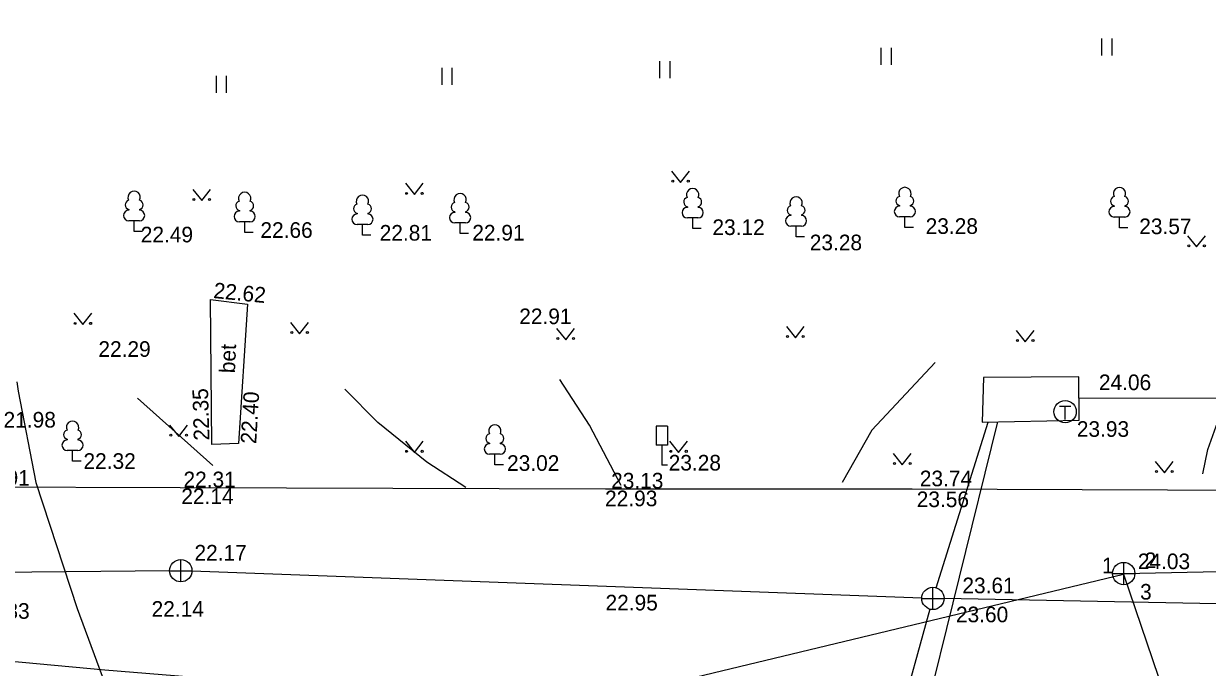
# Model space of a CAD drawing. Extents: x 714391 to 714584, y 6589993 to 6590151.
# Drawn here: x 714490.9 to 714543.9, y 6590093.4 to 6590122.2 of the extents above; entities that cross this region are included whole.
import ezdxf

# ---------------------------------------------------------------- set-up
doc = ezdxf.new("R2010")
doc.units = 0
for name, color, linetype in [('HALJASTUS', 7, 'Continuous'), ('HOONE', 7, 'Continuous'), ('HOONEDET', 7, 'Continuous'), ('HORISONTAAL', 7, 'Continuous'), ('KKAEV', 7, 'Continuous'), ('KORGUS', 7, 'Continuous'), ('KTRASS', 7, 'Continuous'), ('LIIKLUS', 7, 'Continuous'), ('PUU', 7, 'Continuous'), ('SKTRASS', 7, 'Continuous'), ('TEE', 7, 'Continuous'), ('TKAEV', 7, 'Continuous'), ('TORU NR', 7, 'Continuous'), ('TTRASS', 7, 'Continuous'), ('VTRASS', 7, 'Continuous')]:
    doc.layers.add(name, color=color, linetype=linetype)

msp = doc.modelspace()

# ---------------------------------------------------------------- linework, layer by layer
at = {"layer": 'HALJASTUS'}
for p, q in [((714539.182, 6590121.571), (714539.182, 6590120.809)), ((714539.638, 6590121.571), (714539.638, 6590120.809)), ((714529.302, 6590121.151), (714529.302, 6590120.389)), ((714529.758, 6590121.151), (714529.758, 6590120.389)), ((714519.382, 6590120.551), (714519.382, 6590119.789)), ((714519.838, 6590120.551), (714519.838, 6590119.789)), ((714509.622, 6590120.251), (714509.622, 6590119.489)), ((714510.078, 6590120.251), (714510.078, 6590119.489)), ((714499.512, 6590119.891), (714499.512, 6590119.129)), ((714499.968, 6590119.891), (714499.968, 6590119.129)), ((714519.918, 6590115.623), (714520.323, 6590115.118)), ((714520.323, 6590115.118), (714520.718, 6590115.623)), ((714498.47, 6590114.811), (714498.875, 6590114.306)), ((714498.875, 6590114.306), (714499.27, 6590114.811)), ((714507.998, 6590115.082), (714508.403, 6590114.577)), ((714508.403, 6590114.577), (714508.798, 6590115.082)), ((714543.037, 6590112.734), (714543.442, 6590112.229)), ((714543.442, 6590112.229), (714543.837, 6590112.734)), ((714493.142, 6590109.257), (714493.547, 6590108.752)), ((714493.547, 6590108.752), (714493.942, 6590109.257)), ((714502.85, 6590108.85), (714503.255, 6590108.345)), ((714503.255, 6590108.345), (714503.65, 6590108.85)), ((714514.771, 6590108.58), (714515.176, 6590108.075)), ((714515.176, 6590108.075), (714515.571, 6590108.58)), ((714525.066, 6590108.67), (714525.471, 6590108.165)), ((714525.471, 6590108.165), (714525.866, 6590108.67)), ((714535.36, 6590108.489), (714535.765, 6590107.984)), ((714535.765, 6590107.984), (714536.16, 6590108.489)), ((714497.432, 6590104.245), (714497.837, 6590103.74)), ((714497.837, 6590103.74), (714498.232, 6590104.245)), ((714507.998, 6590103.522), (714508.403, 6590103.017)), ((714508.403, 6590103.017), (714508.798, 6590103.522)), ((714519.828, 6590103.522), (714520.233, 6590103.017)), ((714520.233, 6590103.017), (714520.628, 6590103.522)), ((714529.852, 6590102.98), (714530.257, 6590102.475)), ((714530.257, 6590102.475), (714530.652, 6590102.98)), ((714541.592, 6590102.619), (714541.997, 6590102.114)), ((714541.997, 6590102.114), (714542.392, 6590102.619))]:
    msp.add_line(p, q, dxfattribs=at)
for centre, radius in [((714519.97, 6590115.174), 0.0428), ((714520.67, 6590115.174), 0.0452), ((714508.05, 6590114.632), 0.0428), ((714508.75, 6590114.632), 0.0452), ((714498.522, 6590114.361), 0.0428), ((714499.222, 6590114.361), 0.0452), ((714543.089, 6590112.284), 0.0428), ((714543.789, 6590112.284), 0.0452), ((714493.194, 6590108.807), 0.0428), ((714493.894, 6590108.807), 0.0452), ((714502.902, 6590108.401), 0.0428), ((714503.602, 6590108.401), 0.0452), ((714514.823, 6590108.13), 0.0428), ((714515.523, 6590108.13), 0.0452), ((714525.118, 6590108.22), 0.0428), ((714525.818, 6590108.22), 0.0452), ((714535.412, 6590108.039), 0.0428), ((714536.112, 6590108.039), 0.0452), ((714497.484, 6590103.795), 0.0428), ((714498.184, 6590103.795), 0.0452), ((714508.05, 6590103.073), 0.0428), ((714508.75, 6590103.073), 0.0452), ((714519.88, 6590103.073), 0.0428), ((714520.58, 6590103.073), 0.0452), ((714529.904, 6590102.531), 0.0428), ((714530.604, 6590102.531), 0.0452), ((714541.644, 6590102.17), 0.0428), ((714542.344, 6590102.17), 0.0452)]:
    msp.add_circle(centre, radius, dxfattribs=at)
at = {"layer": 'HOONE'}
msp.add_lwpolyline([(714462.976, 6590094.666), (714464.039, 6590094.043), (714487.101, 6590093.963), (714494.525, 6590093.286), (714520.217, 6590091.196), (714543.829, 6590084.007)], dxfattribs=at)
at = {"layer": 'HORISONTAAL'}
for points in [[(714543.72, 6590102.062), (714543.949, 6590103.152), (714543.949, 6590103.152), (714544.314, 6590104.204), (714544.314, 6590104.204), (714544.467, 6590104.547), (714545.44, 6590106.141), (714545.44, 6590106.141), (714545.675, 6590106.435), (714547.022, 6590107.729), (714547.022, 6590107.729)], [(714531.724, 6590107.046), (714528.888, 6590104.019), (714527.567, 6590101.674)], [(714517.657, 6590101.541), (714516.248, 6590104.249), (714514.908, 6590106.294)], [(714510.703, 6590101.446), (714508.954, 6590102.594), (714506.754, 6590104.361), (714505.276, 6590105.864)], [(714499.361, 6590102.44), (714495.986, 6590105.449)]]:
    msp.add_lwpolyline(points, dxfattribs=at)
at = {"layer": 'KKAEV'}
for p, q in [((714497.432, 6590097.723), (714498.432, 6590097.723)), ((714497.932, 6590097.223), (714497.932, 6590098.223)), ((714540.177, 6590097.097), (714540.177, 6590098.097)), ((714539.677, 6590097.597), (714540.677, 6590097.597)), ((714531.628, 6590095.983), (714531.628, 6590096.983)), ((714531.128, 6590096.483), (714532.128, 6590096.483))]:
    msp.add_line(p, q, dxfattribs=at)
for centre in [(714497.932, 6590097.723), (714540.177, 6590097.597), (714531.628, 6590096.483)]:
    msp.add_circle(centre, 0.5, dxfattribs=at)
at = {"layer": 'KTRASS'}
for p, q in [((714505.642, 6590089.275), (714540.165, 6590097.573)), ((714540.165, 6590097.573), (714543.798, 6590086.868))]:
    msp.add_line(p, q, dxfattribs=at)
msp.add_lwpolyline([(714540.177, 6590097.597), (714572.844, 6590098.291), (714583.92, 6590097.517)], dxfattribs=at)
at = {"layer": 'LIIKLUS'}
for p, q in [((714519.237, 6590104.201), (714519.237, 6590103.351)), ((714519.737, 6590104.201), (714519.237, 6590104.201)), ((714519.737, 6590104.201), (714519.737, 6590103.351)), ((714519.737, 6590103.351), (714519.237, 6590103.351)), ((714519.487, 6590103.351), (714519.487, 6590102.451)), ((714519.737, 6590102.451), (714519.487, 6590102.451))]:
    msp.add_line(p, q, dxfattribs=at)
at = {"layer": 'PUU'}
for p, q in [((714495.601, 6590113.908), (714495.601, 6590113.878)), ((714496.081, 6590113.908), (714496.081, 6590113.878)), ((714500.555, 6590113.862), (714500.555, 6590113.832)), ((714501.035, 6590113.862), (714501.035, 6590113.832)), ((714505.831, 6590113.738), (714505.831, 6590113.708)), ((714506.311, 6590113.738), (714506.311, 6590113.708)), ((714510.205, 6590113.811), (714510.205, 6590113.781)), ((714510.685, 6590113.811), (714510.685, 6590113.781)), ((714520.626, 6590114.035), (714520.626, 6590114.005)), ((714521.106, 6590114.035), (714521.106, 6590114.005)), ((714525.258, 6590113.666), (714525.258, 6590113.636)), ((714525.738, 6590113.666), (714525.738, 6590113.636)), ((714530.133, 6590114.085), (714530.133, 6590114.055)), ((714530.613, 6590114.085), (714530.613, 6590114.055)), ((714539.747, 6590114.074), (714539.747, 6590114.044)), ((714540.227, 6590114.074), (714540.227, 6590114.044)), ((714496.081, 6590113.403), (714495.601, 6590113.403)), ((714495.841, 6590112.928), (714495.841, 6590113.403)), ((714501.035, 6590113.357), (714500.555, 6590113.357)), ((714500.795, 6590112.882), (714500.795, 6590113.357)), ((714506.311, 6590113.233), (714505.831, 6590113.233)), ((714506.071, 6590112.758), (714506.071, 6590113.233)), ((714510.685, 6590113.306), (714510.205, 6590113.306)), ((714510.445, 6590112.831), (714510.445, 6590113.306)), ((714521.106, 6590113.53), (714520.626, 6590113.53)), ((714520.866, 6590113.055), (714520.866, 6590113.53)), ((714525.738, 6590113.161), (714525.258, 6590113.161)), ((714525.498, 6590112.686), (714525.498, 6590113.161)), ((714530.613, 6590113.58), (714530.133, 6590113.58)), ((714530.373, 6590113.105), (714530.373, 6590113.58)), ((714530.753, 6590113.105), (714530.373, 6590113.105)), ((714540.227, 6590113.569), (714539.747, 6590113.569)), ((714539.987, 6590113.094), (714539.987, 6590113.569)), ((714540.367, 6590113.094), (714539.987, 6590113.094)), ((714496.221, 6590112.928), (714495.841, 6590112.928)), ((714501.175, 6590112.882), (714500.795, 6590112.882)), ((714506.451, 6590112.758), (714506.071, 6590112.758)), ((714510.825, 6590112.831), (714510.445, 6590112.831)), ((714521.246, 6590113.055), (714520.866, 6590113.055)), ((714525.878, 6590112.686), (714525.498, 6590112.686)), ((714492.843, 6590103.612), (714492.843, 6590103.582)), ((714493.323, 6590103.612), (714493.323, 6590103.582)), ((714493.323, 6590103.107), (714492.843, 6590103.107)), ((714493.083, 6590102.632), (714493.083, 6590103.107)), ((714511.763, 6590103.445), (714511.763, 6590103.415)), ((714512.243, 6590103.445), (714512.243, 6590103.415)), ((714493.463, 6590102.632), (714493.083, 6590102.632)), ((714512.243, 6590102.94), (714511.763, 6590102.94)), ((714512.003, 6590102.465), (714512.003, 6590102.94)), ((714512.383, 6590102.465), (714512.003, 6590102.465))]:
    msp.add_line(p, q, dxfattribs=at)
for centre, radius, start, end in [((714495.841, 6590114.448), 0.277, 332.5799, 207.4201), ((714500.795, 6590114.402), 0.277, 332.5799, 207.4201), ((714520.866, 6590114.575), 0.277, 332.5799, 207.4201), ((714530.373, 6590114.625), 0.277, 332.5799, 207.4201), ((714539.987, 6590114.614), 0.277, 332.5799, 207.4201), ((714495.651, 6590114.116), 0.212, 105.2441, 257.079), ((714496.031, 6590114.116), 0.212, 282.921, 74.7559), ((714500.605, 6590114.07), 0.212, 105.2441, 257.079), ((714500.985, 6590114.07), 0.212, 282.921, 74.7559), ((714505.881, 6590113.946), 0.212, 105.2441, 257.079), ((714506.071, 6590114.278), 0.277, 332.5799, 207.4201), ((714506.261, 6590113.946), 0.212, 282.921, 74.7559), ((714510.255, 6590114.019), 0.212, 105.2441, 257.079), ((714510.445, 6590114.351), 0.277, 332.5799, 207.4201), ((714510.635, 6590114.019), 0.212, 282.921, 74.7559), ((714520.676, 6590114.243), 0.212, 105.2441, 257.079), ((714521.056, 6590114.243), 0.212, 282.921, 74.7559), ((714525.498, 6590114.206), 0.277, 332.5799, 207.4201), ((714530.183, 6590114.293), 0.212, 105.2441, 257.079), ((714530.563, 6590114.293), 0.212, 282.921, 74.7559), ((714539.797, 6590114.281), 0.212, 105.2441, 257.079), ((714540.177, 6590114.281), 0.212, 282.921, 74.7559), ((714495.603, 6590113.641), 0.237, 90, 270), ((714496.078, 6590113.641), 0.237, 270, 90), ((714500.557, 6590113.595), 0.237, 90, 270), ((714501.032, 6590113.595), 0.237, 270, 90), ((714505.833, 6590113.471), 0.237, 90, 270), ((714506.308, 6590113.471), 0.237, 270, 90), ((714510.207, 6590113.544), 0.237, 90, 270), ((714510.682, 6590113.544), 0.237, 270, 90), ((714520.628, 6590113.768), 0.237, 90, 270), ((714521.103, 6590113.768), 0.237, 270, 90), ((714525.26, 6590113.399), 0.237, 90, 270), ((714525.308, 6590113.874), 0.212, 105.2441, 257.079), ((714525.735, 6590113.399), 0.237, 270, 90), ((714525.688, 6590113.874), 0.212, 282.921, 74.7559), ((714530.135, 6590113.818), 0.237, 90, 270), ((714530.61, 6590113.818), 0.237, 270, 90), ((714539.749, 6590113.806), 0.237, 90, 270), ((714540.224, 6590113.806), 0.237, 270, 90), ((714493.083, 6590104.152), 0.277, 332.5799, 207.4201), ((714512.003, 6590103.985), 0.277, 332.5799, 207.4201), ((714492.845, 6590103.345), 0.237, 90, 270), ((714492.893, 6590103.82), 0.212, 105.2441, 257.079), ((714493.32, 6590103.345), 0.237, 270, 90), ((714493.273, 6590103.82), 0.212, 282.921, 74.7559), ((714511.813, 6590103.652), 0.212, 105.2441, 257.079), ((714512.193, 6590103.652), 0.212, 282.921, 74.7559), ((714511.765, 6590103.178), 0.237, 90, 270), ((714512.24, 6590103.178), 0.237, 270, 90)]:
    msp.add_arc(centre, radius, start, end, dxfattribs=at)
at = {"layer": 'SKTRASS'}
for p, q in [((714531.777, 6590096.96), (714534.097, 6590104.384)), ((714497.432, 6590097.718), (714464.189, 6590097.372)), ((714531.128, 6590096.501), (714498.432, 6590097.705)), ((714579.087, 6590095.548), (714532.128, 6590096.473))]:
    msp.add_line(p, q, dxfattribs=at)
msp.add_lwpolyline([(714531.495, 6590096.001), (714522.972, 6590065.168), (714519.718, 6590053.426), (714509.807, 6590017.772), (714505.951, 6590002.864)], dxfattribs=at)
at = {"layer": 'TEE'}
for points in [[(714583.92, 6590101.143), (714565.419, 6590101.225), (714549.748, 6590101.3), (714530.696, 6590101.382), (714516.957, 6590101.382), (714497.906, 6590101.442), (714488.527, 6590101.467), (714476.238, 6590101.479), (714465.964, 6590101.492), (714465.149, 6590101.593), (714461.989, 6590102.308), (714461.271, 6590102.628), (714460.534, 6590103.105), (714459.97, 6590103.737), (714459.406, 6590104.596), (714458.782, 6590106.528), (714458.59, 6590109.02), (714468.756, 6590132.53), (714474.437, 6590144.828), (714474.939, 6590145.152), (714475.17, 6590145.792), (714474.999, 6590146.077), (714477.095, 6590151.075)], [(714500.515, 6590103.431), (714499.32, 6590103.382), (714499.26, 6590109.881), (714500.921, 6590109.666), (714500.515, 6590103.431)]]:
    msp.add_lwpolyline(points, dxfattribs=at)
at = {"layer": 'TKAEV'}
for p, q in [((714537.303, 6590105.098), (714537.803, 6590105.098)), ((714537.553, 6590104.498), (714537.553, 6590105.098))]:
    msp.add_line(p, q, dxfattribs=at)
msp.add_circle((714537.553, 6590104.848), 0.5, dxfattribs=at)
at = {"layer": 'TTRASS'}
msp.add_lwpolyline([(714538.185, 6590104.47), (714538.167, 6590106.414), (714533.889, 6590106.377), (714533.834, 6590104.378)], close=True, dxfattribs=at)
for points in [[(714583.92, 6590105.531), (714538.176, 6590105.447)], [(714510.928, 6590008.703), (714512.829, 6590017.079), (714522.511, 6590055.684), (714522.522, 6590055.681), (714534.537, 6590104.393)]]:
    msp.add_lwpolyline(points, dxfattribs=at)
at = {"layer": 'VTRASS'}
msp.add_lwpolyline([(714490.586, 6590106.186), (714490.652, 6590105.776), (714491.439, 6590101.677), (714493.283, 6590096.028), (714496.505, 6590087.34)], dxfattribs=at)

# ---------------------------------------------------------------- texts
at = {"layer": 'HOONEDET'}
msp.add_text('bet', height=0.7, rotation=87.8184, dxfattribs=at).set_placement((714500.361, 6590106.564))
at = {"layer": 'KORGUS'}
for s, p in [('22.49', (714496.139, 6590112.436)), ('22.66', (714501.499, 6590112.638)), ('22.81', (714506.843, 6590112.514)), ('22.91', (714510.991, 6590112.519)), ('23.12', (714521.751, 6590112.766)), ('23.28', (714531.303, 6590112.816)), ('23.57', (714540.872, 6590112.805)), ('23.28', (714526.112, 6590112.081)), ('22.91', (714513.095, 6590108.771)), ('22.29', (714494.241, 6590107.307)), ('24.06', (714539.065, 6590105.815)), ('21.98', (714489.993, 6590104.138)), ('23.93', (714538.076, 6590103.723)), ('22.32', (714493.573, 6590102.286)), ('23.02', (714512.549, 6590102.198)), ('23.28', (714519.79, 6590102.213)), ('21.91', (714488.827, 6590101.533)), ('22.31', (714498.053, 6590101.462)), ('23.13', (714517.212, 6590101.409)), ('23.74', (714531.041, 6590101.507)), ('22.14', (714497.955, 6590100.712)), ('22.93', (714516.939, 6590100.613)), ('23.56', (714530.903, 6590100.573)), ('22.17', (714498.546, 6590098.179)), ('24.03', (714540.809, 6590097.793)), ('23.61', (714532.949, 6590096.714)), ('22.95', (714516.961, 6590095.944)), ('21.83', (714488.82, 6590095.571)), ('22.14', (714496.624, 6590095.66)), ('23.60', (714532.66, 6590095.414))]:
    msp.add_text(s, height=0.7, dxfattribs=at).set_placement(p)
for s, rotation, p in [('22.62', 354.4064, (714499.374, 6590109.944)), ('22.35', 91.6847, (714499.217, 6590103.566)), ('22.40', 86.5601, (714501.309, 6590103.393))]:
    msp.add_text(s, height=0.7, rotation=rotation, dxfattribs=at).set_placement(p)
at = {"layer": 'TORU NR'}
for s, p in [('1', (714539.2, 6590097.607)), ('2', (714541.114, 6590097.843)), ('3', (714540.91, 6590096.43))]:
    msp.add_text(s, height=0.7, dxfattribs=at).set_placement(p)

doc.saveas('drawing.dxf')
